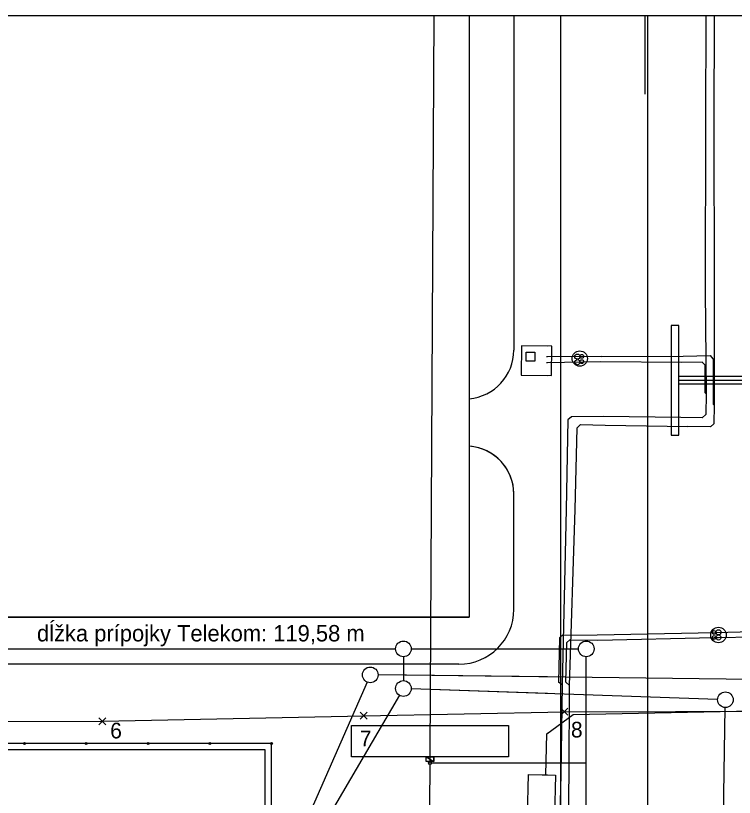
# Model space of a CAD drawing. Extents: x -264053 to -263843, y -1242290 to -1242141.
# Drawn here: x -263988.39 to -263942.56, y -1242190.97 to -1242141.13 of the extents above; entities that cross this region are included whole.
import ezdxf

# ---------------------------------------------------------------- set-up
doc = ezdxf.new("R2010")
doc.units = 0
for name, color, linetype in [('KFA_2D_JESTVUJUCE_IS_DSP', 7, 'Continuous'), ('KFA_2D_SITUACIA_DSP', 7, 'Continuous'), ('KFA_63-2_TELEKOM_PRIPOJKA', 7, 'Continuous'), ('KFA_BODY_CISLO', 7, 'Continuous'), ('KFA_BODY_SYMBOL', 7, 'Continuous'), ('KFA_JESTV_IS_DSP', 7, 'Continuous'), ('KFA_SITUACIA_DSP', 7, 'Continuous'), ('POPIS', 7, 'Continuous'), ('RAM_NA_TLAC_A3_1-500', 7, 'Continuous')]:
    doc.layers.add(name, color=color, linetype=linetype)

msp = doc.modelspace()

# ---------------------------------------------------------------- linework, layer by layer
at = {"layer": 'KFA_2D_JESTVUJUCE_IS_DSP'}
for p, q in [((-263961.72, -1242141.125), (-263961.999, -1242192.922)), ((-263944.373, -1242141.125), (-263944.386, -1242147.884)), ((-263943.845, -1242141.125), (-263943.869, -1242147.889)), ((-263944.386, -1242147.884), (-263944.412, -1242158.664)), ((-263943.869, -1242147.889), (-263943.853, -1242158.652)), ((-263944.412, -1242158.664), (-263944.352, -1242165.249)), ((-263943.853, -1242158.652), (-263943.849, -1242165.958)), ((-263956.13, -1242162.18), (-263956.156, -1242164.04)), ((-263954.192, -1242162.207), (-263956.13, -1242162.18)), ((-263954.218, -1242164.067), (-263954.192, -1242162.207)), ((-263955.831, -1242163.152), (-263955.831, -1242162.573)), ((-263955.831, -1242162.573), (-263955.28, -1242162.573)), ((-263955.28, -1242162.573), (-263955.28, -1242163.152)), ((-263951.019, -1242162.854), (-263954.543, -1242162.888)), ((-263951.019, -1242162.854), (-263945.83, -1242162.832)), ((-263945.83, -1242162.832), (-263944.071, -1242162.801)), ((-263943.916, -1242163.012), (-263944.071, -1242162.801)), ((-263955.28, -1242163.152), (-263955.831, -1242163.152)), ((-263951.079, -1242163.196), (-263954.539, -1242163.255)), ((-263945.899, -1242163.231), (-263951.079, -1242163.196)), ((-263944.614, -1242163.211), (-263945.899, -1242163.231)), ((-263944.447, -1242163.393), (-263944.614, -1242163.211)), ((-263944.447, -1242163.393), (-263944.442, -1242165.164)), ((-263943.914, -1242163.012), (-263943.913, -1242165.895)), ((-263956.156, -1242164.04), (-263954.218, -1242164.067)), ((-263944.442, -1242165.164), (-263944.352, -1242165.249)), ((-263944.442, -1242165.164), (-263944.442, -1242165.164)), ((-263944.352, -1242165.249), (-263944.379, -1242166.564)), ((-263943.913, -1242165.895), (-263943.849, -1242165.958)), ((-263943.913, -1242165.895), (-263943.913, -1242165.895)), ((-263943.849, -1242165.958), (-263943.861, -1242167.143)), ((-263953.167, -1242166.907), (-263953.276, -1242172.621)), ((-263952.942, -1242166.698), (-263953.167, -1242166.907)), ((-263950.896, -1242166.694), (-263952.942, -1242166.698)), ((-263945.968, -1242166.741), (-263950.896, -1242166.694)), ((-263944.61, -1242166.777), (-263945.968, -1242166.741)), ((-263944.379, -1242166.564), (-263944.61, -1242166.777)), ((-263952.715, -1242172.612), (-263952.57, -1242167.416)), ((-263952.57, -1242167.416), (-263952.361, -1242167.2)), ((-263952.361, -1242167.2), (-263950.803, -1242167.244)), ((-263950.803, -1242167.244), (-263945.525, -1242167.325)), ((-263944.087, -1242167.347), (-263945.525, -1242167.325)), ((-263943.861, -1242167.143), (-263944.087, -1242167.347)), ((-263953.276, -1242172.621), (-263953.528, -1242183.799)), ((-263953.067, -1242183.845), (-263952.715, -1242172.612)), ((-263943.779, -1242180.456), (-263932.226, -1242180.187)), ((-263953.71, -1242180.8), (-263953.774, -1242183.629)), ((-263953.71, -1242180.8), (-263953.518, -1242180.617)), ((-263953.518, -1242180.617), (-263951.311, -1242180.614)), ((-263951.311, -1242180.614), (-263943.779, -1242180.456)), ((-263951.265, -1242180.941), (-263943.848, -1242180.778)), ((-263943.848, -1242180.778), (-263943.567, -1242180.776)), ((-263943.567, -1242180.776), (-263932.313, -1242180.597)), ((-263953.31, -1242183.629), (-263953.231, -1242181.09)), ((-263953.231, -1242181.09), (-263953.049, -1242180.917)), ((-263953.049, -1242180.917), (-263951.265, -1242180.941)), ((-263923.234, -1242183.668), (-263965.273, -1242183.165)), ((-263965.974, -1242183.616), (-263969.841, -1242192.426)), ((-263953.528, -1242183.799), (-263953.774, -1242183.629)), ((-263953.528, -1242183.799), (-263953.63, -1242189.514)), ((-263953.067, -1242183.845), (-263953.31, -1242183.629)), ((-263953.083, -1242189.456), (-263953.067, -1242183.845)), ((-263943.628, -1242184.728), (-263963.161, -1242184.046)), ((-263963.914, -1242184.46), (-263969.615, -1242194.201)), ((-263952.832, -1242185.692), (-263937.488, -1242185.363)), ((-263943.675, -1242219.209), (-263943.136, -1242185.245)), ((-263954.509, -1242186.913), (-263952.832, -1242185.692)), ((-263954.57, -1242189.535), (-263954.509, -1242186.913)), ((-263955.775, -1242192.739), (-263955.679, -1242189.503)), ((-263955.679, -1242189.503), (-263953.955, -1242189.552)), ((-263953.955, -1242189.552), (-263954.033, -1242192.766)), ((-263953.63, -1242189.514), (-263953.822, -1242197.849)), ((-263953.266, -1242197.902), (-263953.083, -1242189.456))]:
    msp.add_line(p, q, dxfattribs=at)
for centre, radius in [((-263952.413, -1242162.992), 0.487), ((-263952.568, -1242162.867), 0.164), ((-263952.284, -1242162.851), 0.122), ((-263952.568, -1242163.22), 0.164), ((-263952.284, -1242163.187), 0.122), ((-263943.568, -1242180.617), 0.496), ((-263943.848, -1242180.461), 0.122), ((-263943.567, -1242180.445), 0.164), ((-263943.848, -1242180.778), 0.122), ((-263943.567, -1242180.776), 0.164), ((-263965.773, -1242183.159), 0.5), ((-263963.661, -1242184.028), 0.5), ((-263943.128, -1242184.745), 0.5)]:
    msp.add_circle(centre, radius, dxfattribs=at)
at = {"layer": 'KFA_2D_SITUACIA_DSP'}
for p, q in [((-263959.468, -1242141.125), (-263959.468, -1242179.482)), ((-263956.618, -1242141.125), (-263956.618, -1242162.449)), ((-263953.617, -1242244.458), (-263953.617, -1242141.125)), ((-263948.093, -1242141.125), (-263948.093, -1242219.209)), ((-263918.489, -1242164.132), (-263946.093, -1242164.132)), ((-263918.593, -1242164.382), (-263946.093, -1242164.382)), ((-263918.696, -1242164.632), (-263946.093, -1242164.632)), ((-263959.468, -1242165.549), (-263959.468, -1242165.549)), ((-263959.467, -1242168.582), (-263959.467, -1242168.582)), ((-263956.618, -1242178.982), (-263956.618, -1242171.645)), ((-263956.618, -1242178.982), (-263956.618, -1242178.982)), ((-263959.468, -1242179.482), (-264053.272, -1242179.482)), ((-264053.272, -1242179.482), (-263959.468, -1242179.482)), ((-263959.468, -1242179.482), (-264053.272, -1242179.482)), ((-264013.161, -1242181.5), (-263964.161, -1242181.5)), ((-263963.161, -1242181.5), (-263952.5, -1242181.5)), ((-263963.661, -1242182), (-263963.661, -1242183.528)), ((-263952, -1242222.527), (-263952, -1242182)), ((-263960.118, -1242182.482), (-264034.158, -1242182.482)), ((-263972.068, -1242187.532), (-264053.272, -1242187.532)), ((-263987.883, -1242187.532), (-263987.763, -1242187.532)), ((-263987.823, -1242187.592), (-263987.823, -1242187.472)), ((-263983.944, -1242187.532), (-263983.824, -1242187.532)), ((-263983.884, -1242187.592), (-263983.884, -1242187.472)), ((-263980.006, -1242187.532), (-263979.886, -1242187.532)), ((-263979.946, -1242187.592), (-263979.946, -1242187.472)), ((-263976.067, -1242187.532), (-263975.947, -1242187.532)), ((-263976.007, -1242187.592), (-263976.007, -1242187.472)), ((-263972.128, -1242187.532), (-263972.008, -1242187.532)), ((-263972.068, -1242187.592), (-263972.068, -1242187.472)), ((-263972.068, -1242195.407), (-263972.068, -1242187.532)), ((-263972.468, -1242187.932), (-264042.568, -1242187.932)), ((-263972.468, -1242289.625), (-263972.468, -1242187.932)), ((-263962.218, -1242188.382), (-263961.718, -1242188.382)), ((-263962.218, -1242188.672), (-263962.218, -1242188.382)), ((-263962.218, -1242188.382), (-263961.718, -1242188.672)), ((-263962.218, -1242188.382), (-263961.718, -1242188.672)), ((-263961.718, -1242188.382), (-263962.218, -1242188.382)), ((-263961.718, -1242188.672), (-263962.218, -1242188.672)), ((-263961.868, -1242188.772), (-263952, -1242188.772)), ((-263961.718, -1242188.382), (-263961.718, -1242188.672)), ((-263961.718, -1242188.672), (-263961.718, -1242188.382))]:
    msp.add_line(p, q, dxfattribs=at)
for points in [[(-263946.093, -1242167.882), (-263946.093, -1242160.882), (-263946.593, -1242160.882), (-263946.593, -1242167.882)], [(-263966.968, -1242186.382), (-263956.968, -1242186.382), (-263956.968, -1242188.382), (-263966.968, -1242188.382)]]:
    msp.add_lwpolyline(points, close=True, dxfattribs=at)
msp.add_lwpolyline([(-263956.618, -1242178.982), (-263956.618, -1242171.626), (-263956.64, -1242171.257), (-263956.707, -1242170.894), (-263956.87, -1242170.411), (-263957.158, -1242169.893), (-263957.435, -1242169.549), (-263957.705, -1242169.291), (-263958.077, -1242169.024), (-263958.45, -1242168.829), (-263958.842, -1242168.69), (-263959.056, -1242168.638), (-263959.273, -1242168.601), (-263959.468, -1242168.582)], dxfattribs=at)
for centre, radius in [((-263963.661, -1242181.5), 0.5), ((-263952, -1242181.5), 0.5), ((-263987.823, -1242187.532), 0.06), ((-263983.884, -1242187.532), 0.06), ((-263979.946, -1242187.532), 0.06), ((-263976.007, -1242187.532), 0.06), ((-263972.068, -1242187.532), 0.06), ((-263961.968, -1242188.772), 0.1)]:
    msp.add_circle(centre, radius, dxfattribs=at)
for centre, radius, start, end in [((-263959.738, -1242162.441), 3.12, 274.9637, 359.8482), ((-263959.668, -1242171.626), 3.05, 359.6441, 86.2155), ((-263960.118, -1242178.982), 3.5, 270, 0)]:
    msp.add_arc(centre, radius, start, end, dxfattribs=at)
at = {"layer": 'KFA_63-2_TELEKOM_PRIPOJKA'}
msp.add_lwpolyline([(-264029.881, -1242182.077), (-264029.905, -1242185.793), (-264029.004, -1242186.266), (-264023.98, -1242186.128), (-264003.402, -1242186.128), (-263982.858, -1242186.12), (-263966.19, -1242185.767), (-263953.396, -1242185.506), (-263939.258, -1242185.468), (-263919.631, -1242185.484), (-263914.168, -1242185.372)], dxfattribs=at)
at = {"layer": 'KFA_BODY_SYMBOL'}
for p, q in [((-263953.617, -1242185.727), (-263953.175, -1242185.285)), ((-263953.175, -1242185.727), (-263953.617, -1242185.285)), ((-263966.411, -1242185.988), (-263965.969, -1242185.546)), ((-263965.969, -1242185.988), (-263966.411, -1242185.546)), ((-263983.079, -1242186.341), (-263982.637, -1242185.899)), ((-263982.637, -1242186.341), (-263983.079, -1242185.899))]:
    msp.add_line(p, q, dxfattribs=at)
at = {"layer": 'KFA_JESTV_IS_DSP'}
for p, q in [((-263961.72, -1242141.125), (-263961.999, -1242192.922)), ((-263956.13, -1242162.18), (-263956.156, -1242164.04)), ((-263954.47, -1242162.203), (-263956.13, -1242162.18)), ((-263955.831, -1242163.152), (-263955.831, -1242162.573)), ((-263955.831, -1242162.573), (-263955.28, -1242162.573)), ((-263955.28, -1242162.573), (-263955.28, -1242163.152)), ((-263954.47, -1242162.887), (-263954.543, -1242162.888)), ((-263955.28, -1242163.152), (-263955.831, -1242163.152)), ((-263954.47, -1242163.254), (-263954.539, -1242163.255)), ((-263956.156, -1242164.04), (-263954.47, -1242164.064)), ((-263954.47, -1242183.294), (-263965.273, -1242183.165)), ((-263965.974, -1242183.616), (-263969.841, -1242192.426)), ((-263954.47, -1242184.349), (-263963.161, -1242184.046)), ((-263963.914, -1242184.46), (-263969.615, -1242194.201)), ((-263954.57, -1242189.535), (-263954.509, -1242186.913)), ((-263954.509, -1242186.913), (-263954.47, -1242186.884)), ((-263955.775, -1242192.739), (-263955.679, -1242189.503)), ((-263955.679, -1242189.503), (-263954.47, -1242189.537))]:
    msp.add_line(p, q, dxfattribs=at)
for centre in [(-263965.773, -1242183.159), (-263963.661, -1242184.028)]:
    msp.add_circle(centre, 0.5, dxfattribs=at)
at = {"layer": 'KFA_SITUACIA_DSP'}
for p, q in [((-263959.468, -1242141.125), (-263959.468, -1242179.482)), ((-263956.618, -1242141.125), (-263956.618, -1242162.449)), ((-263959.468, -1242165.549), (-263959.468, -1242165.549)), ((-263959.467, -1242168.582), (-263959.467, -1242168.582)), ((-263956.618, -1242178.982), (-263956.618, -1242171.645)), ((-263956.618, -1242178.982), (-263956.618, -1242178.982)), ((-263959.468, -1242179.482), (-264053.272, -1242179.482)), ((-264053.272, -1242179.482), (-263959.468, -1242179.482)), ((-263959.468, -1242179.482), (-264053.272, -1242179.482)), ((-264013.161, -1242181.5), (-263964.161, -1242181.5)), ((-263963.161, -1242181.5), (-263954.47, -1242181.5)), ((-263963.661, -1242182), (-263963.661, -1242183.528)), ((-263960.118, -1242182.482), (-264034.158, -1242182.482)), ((-263972.068, -1242187.532), (-264053.272, -1242187.532)), ((-263987.883, -1242187.532), (-263987.763, -1242187.532)), ((-263987.823, -1242187.592), (-263987.823, -1242187.472)), ((-263983.944, -1242187.532), (-263983.824, -1242187.532)), ((-263983.884, -1242187.592), (-263983.884, -1242187.472)), ((-263980.006, -1242187.532), (-263979.886, -1242187.532)), ((-263979.946, -1242187.592), (-263979.946, -1242187.472)), ((-263976.067, -1242187.532), (-263975.947, -1242187.532)), ((-263976.007, -1242187.592), (-263976.007, -1242187.472)), ((-263972.128, -1242187.532), (-263972.008, -1242187.532)), ((-263972.068, -1242187.592), (-263972.068, -1242187.472)), ((-263972.068, -1242195.407), (-263972.068, -1242187.532)), ((-263972.468, -1242187.932), (-264042.568, -1242187.932)), ((-263972.468, -1242289.625), (-263972.468, -1242187.932)), ((-263962.218, -1242188.382), (-263961.718, -1242188.382)), ((-263962.218, -1242188.672), (-263962.218, -1242188.382)), ((-263962.218, -1242188.382), (-263961.718, -1242188.672)), ((-263962.218, -1242188.382), (-263961.718, -1242188.672)), ((-263961.718, -1242188.382), (-263962.218, -1242188.382)), ((-263961.718, -1242188.672), (-263962.218, -1242188.672)), ((-263961.868, -1242188.772), (-263954.47, -1242188.772)), ((-263961.718, -1242188.382), (-263961.718, -1242188.672)), ((-263961.718, -1242188.672), (-263961.718, -1242188.382))]:
    msp.add_line(p, q, dxfattribs=at)
msp.add_lwpolyline([(-263956.618, -1242178.982), (-263956.618, -1242171.626), (-263956.64, -1242171.257), (-263956.707, -1242170.894), (-263956.87, -1242170.411), (-263957.158, -1242169.893), (-263957.435, -1242169.549), (-263957.705, -1242169.291), (-263958.077, -1242169.024), (-263958.45, -1242168.829), (-263958.842, -1242168.69), (-263959.056, -1242168.638), (-263959.273, -1242168.601), (-263959.468, -1242168.582)], dxfattribs=at)
msp.add_lwpolyline([(-263966.968, -1242186.382), (-263956.968, -1242186.382), (-263956.968, -1242188.382), (-263966.968, -1242188.382)], close=True, dxfattribs=at)
for centre, radius in [((-263963.661, -1242181.5), 0.5), ((-263987.823, -1242187.532), 0.06), ((-263983.884, -1242187.532), 0.06), ((-263979.946, -1242187.532), 0.06), ((-263976.007, -1242187.532), 0.06), ((-263972.068, -1242187.532), 0.06), ((-263961.968, -1242188.772), 0.1)]:
    msp.add_circle(centre, radius, dxfattribs=at)
for centre, radius, start, end in [((-263959.738, -1242162.441), 3.12, 274.9637, 359.8482), ((-263959.668, -1242171.626), 3.05, 359.6441, 86.2155), ((-263960.118, -1242178.982), 3.5, 270, 0)]:
    msp.add_arc(centre, radius, start, end, dxfattribs=at)
at = {"layer": 'RAM_NA_TLAC_A3_1-500'}
msp.add_line((-263948.272, -1242141.125), (-263948.272, -1242146.125), dxfattribs=at)
msp.add_lwpolyline([(-264053.272, -1242141.125), (-263843.272, -1242141.125), (-263843.272, -1242289.625), (-264053.272, -1242289.625)], close=True, dxfattribs=at)

# ---------------------------------------------------------------- texts
at = {"layer": 'KFA_BODY_CISLO'}
for s, p in [('6', (-263982.357, -1242187.21)), ('8', (-263952.977, -1242187.151)), ('7', (-263966.439, -1242187.708))]:
    msp.add_text(s, height=1, dxfattribs=at).set_placement(p)
at = {"layer": 'POPIS'}
msp.add_text('dĺžka prípojky Telekom: 119,58 m', height=1.045, dxfattribs=at).set_placement((-263987.027, -1242181.027))

doc.saveas('drawing.dxf')
